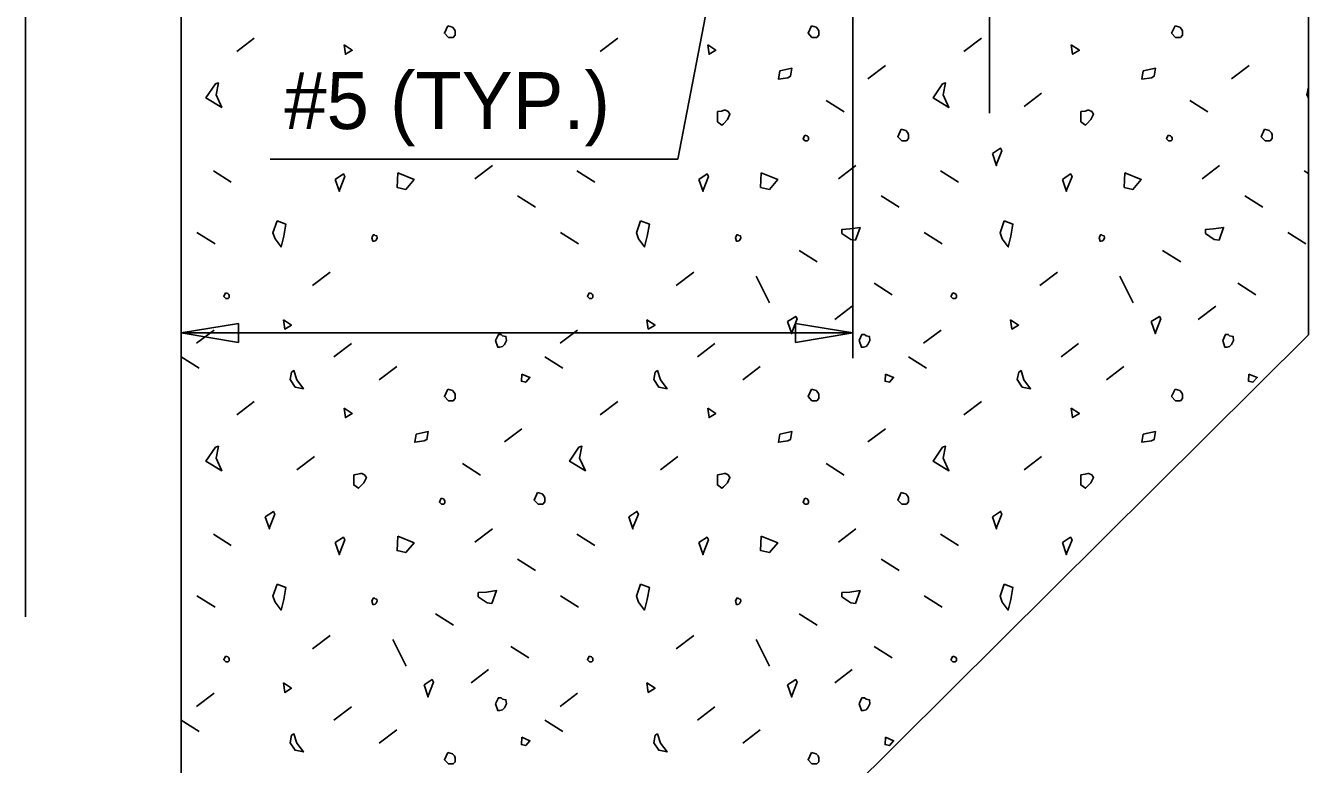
# Model space of a CAD drawing. Extents: x 0 to 136, y 0 to 94.
# Drawn here: x 37.05 to 51.13, y 22.74 to 30.85 of the extents above; entities that cross this region are included whole.
import ezdxf

# ---------------------------------------------------------------- set-up
doc = ezdxf.new("R2010")
doc.units = 0
for name, color, linetype in [('BRDG_ANNO_General-Notes', 7, 'Continuous'), ('BRDG_BASE_Dtlctrln', 7, 'Continuous'), ('BRDG_BASE_Obj-Line', 7, 'Continuous'), ('BRDG_BASE_Pattern', 7, 'Continuous'), ('BRDG_BASE_Rebar', 7, 'Continuous')]:
    doc.layers.add(name, color=color, linetype=linetype)

msp = doc.modelspace()

# ---------------------------------------------------------------- linework, layer by layer
at = {"layer": 'BRDG_ANNO_General-Notes'}
for p, q in [((44.206, 29.387), (44.732, 32.108)), ((46.13, 27.2), (46.13, 31.185)), ((39.731, 29.387), (44.206, 29.387)), ((38.755, 27.478), (39.385, 27.583)), ((38.755, 27.478), (46.13, 27.478)), ((39.385, 27.373), (38.755, 27.478)), ((39.385, 27.583), (39.385, 27.373)), ((45.5, 27.373), (45.5, 27.583)), ((45.5, 27.583), (46.13, 27.478)), ((46.13, 27.478), (45.5, 27.373))]:
    msp.add_line(p, q, dxfattribs=at)
at = {"layer": 'BRDG_BASE_Dtlctrln'}
msp.add_line((37.047, 24.363), (37.047, 38.909), dxfattribs=at)
at = {"layer": 'BRDG_BASE_Obj-Line'}
for p, q in [((38.755, 31.47), (38.755, 15.253)), ((51.13, 31.137), (51.13, 27.457)), ((51.13, 27.457), (43.13, 19.511))]:
    msp.add_line(p, q, dxfattribs=at)
at = {"layer": 'BRDG_BASE_Pattern'}
for p, q in [((39.556, 30.714), (39.364, 30.567)), ((43.548, 30.714), (43.356, 30.567)), ((47.54, 30.714), (47.348, 30.567)), ((46.488, 30.415), (46.295, 30.269)), ((50.479, 30.415), (50.287, 30.269)), ((45.835, 30.031), (46.034, 29.906)), ((48.2, 30.109), (48.008, 29.963)), ((49.827, 30.031), (50.025, 29.906)), ((42.171, 29.316), (41.979, 29.17)), ((46.163, 29.316), (45.971, 29.17)), ((50.155, 29.316), (49.963, 29.17)), ((39.108, 29.256), (39.305, 29.132)), ((43.099, 29.256), (43.297, 29.132)), ((47.091, 29.256), (47.289, 29.132)), ((51.083, 29.256), (51.13, 29.227)), ((42.447, 28.983), (42.645, 28.858)), ((46.439, 28.983), (46.637, 28.858)), ((50.431, 28.983), (50.629, 28.858)), ((38.928, 28.58), (39.126, 28.455)), ((42.92, 28.58), (43.117, 28.455)), ((46.912, 28.58), (47.109, 28.455)), ((50.903, 28.58), (51.101, 28.455)), ((45.538, 28.384), (45.736, 28.259)), ((49.53, 28.384), (49.728, 28.259)), ((40.39, 28.145), (40.198, 27.999)), ((44.382, 28.145), (44.19, 27.999)), ((45.068, 28.101), (45.215, 27.807)), ((48.374, 28.145), (48.182, 27.999)), ((49.06, 28.101), (49.207, 27.807)), ((46.364, 28.023), (46.562, 27.898)), ((50.356, 28.023), (50.554, 27.898)), ((46.122, 27.77), (45.93, 27.624)), ((50.114, 27.77), (49.921, 27.624)), ((39.115, 27.51), (38.923, 27.364)), ((43.107, 27.51), (42.914, 27.364)), ((47.099, 27.51), (46.906, 27.364)), ((40.624, 27.363), (40.431, 27.216)), ((44.615, 27.363), (44.423, 27.216)), ((48.607, 27.363), (48.415, 27.216)), ((38.755, 27.216), (38.953, 27.091)), ((42.747, 27.216), (42.945, 27.091)), ((46.739, 27.216), (46.937, 27.091)), ((41.121, 27.108), (40.928, 26.962)), ((45.113, 27.108), (44.92, 26.962)), ((49.105, 27.108), (48.912, 26.962)), ((39.556, 26.726), (39.364, 26.58)), ((43.548, 26.726), (43.356, 26.58)), ((47.54, 26.726), (47.348, 26.58)), ((42.496, 26.427), (42.303, 26.281)), ((46.488, 26.427), (46.295, 26.281)), ((40.217, 26.121), (40.024, 25.975)), ((44.208, 26.121), (44.016, 25.975)), ((48.2, 26.121), (48.008, 25.975)), ((41.844, 26.043), (42.042, 25.918)), ((45.835, 26.043), (46.034, 25.918)), ((39.108, 25.269), (39.305, 25.144)), ((42.171, 25.328), (41.979, 25.182)), ((43.099, 25.269), (43.297, 25.144)), ((46.163, 25.328), (45.971, 25.182)), ((47.091, 25.269), (47.289, 25.144)), ((42.447, 24.995), (42.645, 24.87)), ((46.439, 24.995), (46.637, 24.87)), ((38.928, 24.593), (39.126, 24.467)), ((42.92, 24.593), (43.117, 24.467)), ((46.912, 24.593), (47.109, 24.467)), ((41.547, 24.396), (41.744, 24.271)), ((45.538, 24.396), (45.736, 24.271)), ((40.39, 24.158), (40.198, 24.011)), ((41.077, 24.113), (41.223, 23.819)), ((44.382, 24.158), (44.19, 24.011)), ((45.068, 24.113), (45.215, 23.819)), ((42.372, 24.035), (42.57, 23.91)), ((46.364, 24.035), (46.562, 23.91)), ((42.13, 23.782), (41.938, 23.636)), ((46.122, 23.782), (45.93, 23.636)), ((39.115, 23.523), (38.923, 23.376)), ((43.107, 23.523), (42.914, 23.376)), ((40.624, 23.375), (40.431, 23.228)), ((44.615, 23.375), (44.423, 23.228)), ((38.755, 23.228), (38.953, 23.103)), ((41.121, 23.121), (40.928, 22.974)), ((42.747, 23.228), (42.945, 23.103)), ((45.113, 23.121), (44.92, 22.974))]:
    msp.add_line(p, q, dxfattribs=at)
for points in [[(41.682, 30.848), (41.645, 30.767), (41.688, 30.722), (41.741, 30.722), (41.763, 30.746), (41.763, 30.789), (41.756, 30.81), (41.733, 30.834)], [(45.674, 30.848), (45.637, 30.767), (45.68, 30.722), (45.733, 30.722), (45.755, 30.746), (45.755, 30.789), (45.748, 30.81), (45.725, 30.834)], [(49.666, 30.848), (49.629, 30.767), (49.672, 30.722), (49.725, 30.722), (49.747, 30.746), (49.747, 30.789), (49.74, 30.81), (49.717, 30.834)], [(40.543, 30.64), (40.558, 30.537), (40.632, 30.581)], [(44.535, 30.64), (44.55, 30.537), (44.624, 30.581)], [(48.527, 30.64), (48.542, 30.537), (48.616, 30.581)], [(45.326, 30.354), (45.311, 30.265), (45.415, 30.28), (45.444, 30.295), (45.459, 30.383)], [(49.318, 30.354), (49.303, 30.265), (49.407, 30.28), (49.436, 30.295), (49.451, 30.383)], [(39.13, 30.211), (39.027, 30.057), (39.2, 29.953), (39.137, 30.093), (39.164, 30.222)], [(47.114, 30.211), (47.011, 30.057), (47.184, 29.953), (47.121, 30.093), (47.147, 30.222)], [(44.641, 29.908), (44.641, 29.796), (44.692, 29.76), (44.707, 29.775), (44.751, 29.819), (44.78, 29.878), (44.759, 29.908), (44.729, 29.922), (44.715, 29.922), (44.686, 29.914)], [(48.633, 29.908), (48.633, 29.796), (48.684, 29.76), (48.699, 29.775), (48.742, 29.819), (48.772, 29.878), (48.751, 29.908), (48.721, 29.922), (48.707, 29.922), (48.678, 29.914)], [(45.6, 29.65), (45.582, 29.61), (45.603, 29.587), (45.63, 29.587), (45.641, 29.599), (45.641, 29.621), (45.637, 29.632), (45.626, 29.643)], [(46.658, 29.713), (46.621, 29.632), (46.665, 29.587), (46.717, 29.587), (46.739, 29.611), (46.739, 29.654), (46.732, 29.675), (46.709, 29.699)], [(49.592, 29.65), (49.574, 29.61), (49.595, 29.587), (49.622, 29.587), (49.633, 29.599), (49.633, 29.621), (49.629, 29.632), (49.618, 29.643)], [(50.65, 29.713), (50.613, 29.632), (50.656, 29.587), (50.709, 29.587), (50.731, 29.611), (50.731, 29.654), (50.724, 29.675), (50.701, 29.699)], [(47.661, 29.447), (47.707, 29.314), (47.707, 29.329), (47.766, 29.477), (47.751, 29.506)], [(40.446, 29.164), (40.492, 29.032), (40.492, 29.046), (40.551, 29.194), (40.536, 29.223)], [(41.132, 29.235), (41.125, 29.076), (41.22, 29.054), (41.312, 29.161)], [(44.438, 29.164), (44.484, 29.032), (44.484, 29.046), (44.543, 29.194), (44.528, 29.223)], [(45.123, 29.235), (45.116, 29.076), (45.212, 29.054), (45.304, 29.161)], [(48.43, 29.164), (48.476, 29.032), (48.476, 29.046), (48.535, 29.194), (48.52, 29.223)], [(49.115, 29.235), (49.108, 29.076), (49.204, 29.054), (49.296, 29.161)], [(39.807, 28.71), (39.762, 28.577), (39.785, 28.511), (39.851, 28.422), (39.88, 28.54), (39.903, 28.673)], [(43.799, 28.71), (43.754, 28.577), (43.777, 28.511), (43.843, 28.422), (43.872, 28.54), (43.895, 28.673)], [(46.097, 28.622), (46.009, 28.615), (46.009, 28.57), (46.105, 28.504), (46.157, 28.497), (46.208, 28.637)], [(47.791, 28.71), (47.746, 28.577), (47.769, 28.511), (47.835, 28.422), (47.864, 28.54), (47.886, 28.673)], [(50.089, 28.622), (50.001, 28.615), (50.001, 28.57), (50.097, 28.504), (50.149, 28.497), (50.2, 28.637)], [(40.849, 28.521), (40.86, 28.484), (40.871, 28.484), (40.886, 28.488), (40.897, 28.498), (40.907, 28.521), (40.904, 28.543), (40.886, 28.547), (40.878, 28.554), (40.863, 28.554)], [(44.84, 28.521), (44.852, 28.484), (44.863, 28.484), (44.878, 28.488), (44.889, 28.498), (44.899, 28.521), (44.896, 28.543), (44.878, 28.547), (44.87, 28.554), (44.855, 28.554)], [(48.832, 28.521), (48.844, 28.484), (48.855, 28.484), (48.87, 28.488), (48.88, 28.498), (48.891, 28.521), (48.888, 28.543), (48.87, 28.547), (48.862, 28.554), (48.847, 28.554)], [(39.241, 27.918), (39.222, 27.878), (39.244, 27.855), (39.271, 27.855), (39.281, 27.867), (39.281, 27.889), (39.278, 27.899), (39.266, 27.911)], [(43.233, 27.918), (43.214, 27.878), (43.236, 27.855), (43.262, 27.855), (43.273, 27.867), (43.273, 27.889), (43.27, 27.899), (43.258, 27.911)], [(47.225, 27.918), (47.206, 27.878), (47.228, 27.855), (47.254, 27.855), (47.265, 27.867), (47.265, 27.889), (47.262, 27.899), (47.25, 27.911)], [(39.877, 27.623), (39.891, 27.52), (39.965, 27.564)], [(43.868, 27.623), (43.883, 27.52), (43.957, 27.564)], [(45.413, 27.602), (45.458, 27.469), (45.458, 27.483), (45.517, 27.631), (45.502, 27.66)], [(47.86, 27.623), (47.875, 27.52), (47.949, 27.564)], [(49.404, 27.602), (49.45, 27.469), (49.45, 27.483), (49.509, 27.631), (49.494, 27.66)], [(42.207, 27.395), (42.23, 27.321), (42.252, 27.321), (42.282, 27.328), (42.303, 27.35), (42.325, 27.395), (42.319, 27.439), (42.282, 27.446), (42.266, 27.462), (42.237, 27.462)], [(46.199, 27.395), (46.222, 27.321), (46.244, 27.321), (46.274, 27.328), (46.295, 27.35), (46.317, 27.395), (46.311, 27.439), (46.274, 27.446), (46.258, 27.462), (46.229, 27.462)], [(50.191, 27.395), (50.214, 27.321), (50.235, 27.321), (50.265, 27.328), (50.287, 27.35), (50.309, 27.395), (50.303, 27.439), (50.265, 27.446), (50.25, 27.462), (50.22, 27.462)], [(39.966, 27.049), (39.95, 26.966), (40.005, 26.884), (40.097, 26.866), (40.024, 26.964), (39.992, 27.065)], [(43.958, 27.049), (43.942, 26.966), (43.997, 26.884), (44.089, 26.866), (44.016, 26.964), (43.984, 27.065)], [(47.95, 27.049), (47.934, 26.966), (47.989, 26.884), (48.081, 26.866), (48.007, 26.964), (47.976, 27.065)], [(42.494, 27.027), (42.49, 26.948), (42.538, 26.936), (42.584, 26.99)], [(46.486, 27.027), (46.482, 26.948), (46.53, 26.936), (46.576, 26.99)], [(50.478, 27.027), (50.474, 26.948), (50.522, 26.936), (50.568, 26.99)], [(41.682, 26.86), (41.645, 26.779), (41.688, 26.734), (41.741, 26.734), (41.763, 26.758), (41.763, 26.801), (41.756, 26.822), (41.733, 26.846)], [(45.674, 26.86), (45.637, 26.779), (45.68, 26.734), (45.733, 26.734), (45.755, 26.758), (45.755, 26.801), (45.748, 26.822), (45.725, 26.846)], [(49.666, 26.86), (49.629, 26.779), (49.672, 26.734), (49.725, 26.734), (49.747, 26.758), (49.747, 26.801), (49.74, 26.822), (49.717, 26.846)], [(40.543, 26.652), (40.558, 26.549), (40.632, 26.594)], [(44.535, 26.652), (44.55, 26.549), (44.624, 26.594)], [(48.527, 26.652), (48.542, 26.549), (48.616, 26.594)], [(41.334, 26.366), (41.319, 26.278), (41.423, 26.292), (41.452, 26.307), (41.467, 26.395)], [(45.326, 26.366), (45.311, 26.278), (45.415, 26.292), (45.444, 26.307), (45.459, 26.395)], [(49.318, 26.366), (49.303, 26.278), (49.407, 26.292), (49.436, 26.307), (49.451, 26.395)], [(39.13, 26.223), (39.027, 26.069), (39.2, 25.965), (39.137, 26.105), (39.164, 26.234)], [(43.122, 26.223), (43.019, 26.069), (43.192, 25.965), (43.129, 26.105), (43.155, 26.234)], [(47.114, 26.223), (47.011, 26.069), (47.184, 25.965), (47.121, 26.105), (47.147, 26.234)], [(40.649, 25.92), (40.649, 25.809), (40.7, 25.773), (40.715, 25.787), (40.759, 25.832), (40.788, 25.891), (40.767, 25.92), (40.737, 25.934), (40.723, 25.934), (40.694, 25.926)], [(44.641, 25.92), (44.641, 25.809), (44.692, 25.773), (44.707, 25.787), (44.751, 25.832), (44.78, 25.891), (44.759, 25.92), (44.729, 25.934), (44.715, 25.934), (44.686, 25.926)], [(48.633, 25.92), (48.633, 25.809), (48.684, 25.773), (48.699, 25.787), (48.742, 25.832), (48.772, 25.891), (48.751, 25.92), (48.721, 25.934), (48.707, 25.934), (48.678, 25.926)], [(41.608, 25.663), (41.59, 25.622), (41.612, 25.6), (41.638, 25.6), (41.649, 25.612), (41.649, 25.633), (41.645, 25.644), (41.634, 25.656)], [(42.666, 25.725), (42.629, 25.644), (42.673, 25.599), (42.726, 25.599), (42.747, 25.623), (42.747, 25.666), (42.74, 25.687), (42.717, 25.711)], [(45.6, 25.663), (45.582, 25.622), (45.603, 25.6), (45.63, 25.6), (45.641, 25.612), (45.641, 25.633), (45.637, 25.644), (45.626, 25.656)], [(46.658, 25.725), (46.621, 25.644), (46.665, 25.599), (46.717, 25.599), (46.739, 25.623), (46.739, 25.666), (46.732, 25.687), (46.709, 25.711)], [(39.678, 25.46), (39.723, 25.327), (39.723, 25.341), (39.782, 25.489), (39.767, 25.518)], [(43.669, 25.46), (43.715, 25.327), (43.715, 25.341), (43.774, 25.489), (43.759, 25.518)], [(47.661, 25.46), (47.707, 25.327), (47.707, 25.341), (47.766, 25.489), (47.751, 25.518)], [(40.446, 25.177), (40.492, 25.044), (40.492, 25.058), (40.551, 25.206), (40.536, 25.236)], [(41.132, 25.247), (41.125, 25.089), (41.22, 25.067), (41.312, 25.173)], [(44.438, 25.177), (44.484, 25.044), (44.484, 25.058), (44.543, 25.206), (44.528, 25.236)], [(45.123, 25.247), (45.116, 25.089), (45.212, 25.067), (45.304, 25.173)], [(48.43, 25.177), (48.476, 25.044), (48.476, 25.058), (48.535, 25.206), (48.52, 25.236)], [(39.807, 24.722), (39.762, 24.59), (39.785, 24.523), (39.851, 24.435), (39.88, 24.553), (39.903, 24.685)], [(42.106, 24.634), (42.017, 24.627), (42.017, 24.583), (42.113, 24.517), (42.165, 24.509), (42.217, 24.649)], [(43.799, 24.722), (43.754, 24.59), (43.777, 24.523), (43.843, 24.435), (43.872, 24.553), (43.895, 24.685)], [(46.097, 24.634), (46.009, 24.627), (46.009, 24.583), (46.105, 24.517), (46.157, 24.509), (46.208, 24.649)], [(47.791, 24.722), (47.746, 24.59), (47.769, 24.523), (47.835, 24.435), (47.864, 24.553), (47.886, 24.685)], [(40.849, 24.533), (40.86, 24.496), (40.871, 24.496), (40.886, 24.5), (40.897, 24.511), (40.907, 24.533), (40.904, 24.555), (40.886, 24.559), (40.878, 24.567), (40.863, 24.567)], [(44.84, 24.533), (44.852, 24.496), (44.863, 24.496), (44.878, 24.5), (44.889, 24.511), (44.899, 24.533), (44.896, 24.555), (44.878, 24.559), (44.87, 24.567), (44.855, 24.567)], [(39.241, 23.931), (39.222, 23.89), (39.244, 23.868), (39.271, 23.868), (39.281, 23.879), (39.281, 23.901), (39.278, 23.912), (39.266, 23.923)], [(43.233, 23.931), (43.214, 23.89), (43.236, 23.868), (43.262, 23.868), (43.273, 23.879), (43.273, 23.901), (43.27, 23.912), (43.258, 23.923)], [(47.225, 23.931), (47.206, 23.89), (47.228, 23.868), (47.254, 23.868), (47.265, 23.879), (47.265, 23.901), (47.262, 23.912), (47.25, 23.923)], [(41.421, 23.614), (41.466, 23.481), (41.466, 23.495), (41.525, 23.643), (41.51, 23.673)], [(45.413, 23.614), (45.458, 23.481), (45.458, 23.495), (45.517, 23.643), (45.502, 23.673)], [(39.877, 23.636), (39.891, 23.532), (39.965, 23.577)], [(43.868, 23.636), (43.883, 23.532), (43.957, 23.577)], [(42.207, 23.407), (42.23, 23.333), (42.252, 23.333), (42.282, 23.341), (42.303, 23.362), (42.325, 23.407), (42.319, 23.451), (42.282, 23.459), (42.266, 23.474), (42.237, 23.474)], [(46.199, 23.407), (46.222, 23.333), (46.244, 23.333), (46.274, 23.341), (46.295, 23.362), (46.317, 23.407), (46.311, 23.451), (46.274, 23.459), (46.258, 23.474), (46.229, 23.474)], [(39.966, 23.061), (39.95, 22.978), (40.005, 22.897), (40.097, 22.878), (40.024, 22.976), (39.992, 23.077)], [(42.494, 23.039), (42.49, 22.96), (42.538, 22.949), (42.584, 23.002)], [(43.958, 23.061), (43.942, 22.978), (43.997, 22.897), (44.089, 22.878), (44.016, 22.976), (43.984, 23.077)], [(46.486, 23.039), (46.482, 22.96), (46.53, 22.949), (46.576, 23.002)], [(41.682, 22.872), (41.645, 22.792), (41.688, 22.747), (41.741, 22.747), (41.763, 22.77), (41.763, 22.813), (41.756, 22.835), (41.733, 22.858)], [(45.674, 22.872), (45.637, 22.792), (45.68, 22.747), (45.733, 22.747), (45.755, 22.77), (45.755, 22.813), (45.748, 22.835), (45.725, 22.858)]]:
    msp.add_lwpolyline(points, close=True, dxfattribs=at)
msp.add_lwpolyline([(51.13, 30.055), (51.113, 30.093), (51.13, 30.176)], dxfattribs=at)
at = {"layer": 'BRDG_BASE_Rebar'}
msp.add_line((47.63, 29.892), (47.63, 34.733), dxfattribs=at)

# ---------------------------------------------------------------- texts
at = {"layer": 'BRDG_ANNO_General-Notes'}
msp.add_text('#5 (TYP.)', height=0.625, dxfattribs=at).set_placement((39.886, 29.716))

doc.saveas('drawing.dxf')
